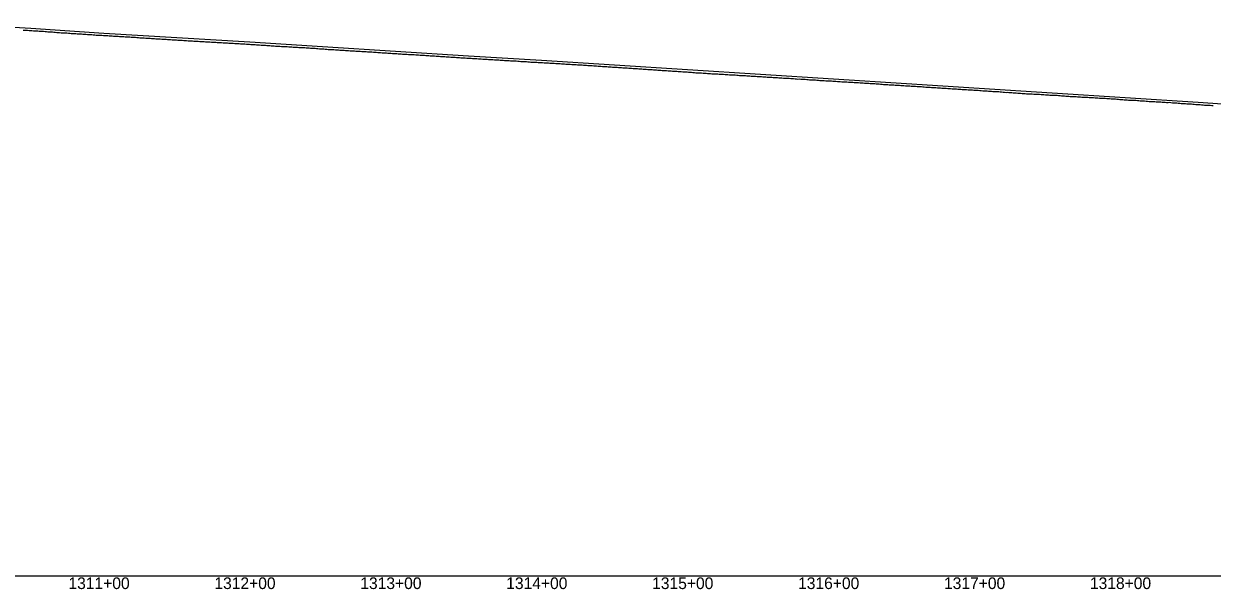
# Model space of a CAD drawing. Extents: x -3793 to 50787, y -1075 to 6138.
# Drawn here: x 18366 to 19180, y 2991 to 3378 of the extents above; entities that cross this region are included whole.
import ezdxf

# ---------------------------------------------------------------- set-up
doc = ezdxf.new("R2010")
doc.units = 0
for name, color, linetype in [('RD_DDB_Profile_EX', 7, 'Continuous'), ('RD_DDB_Profile_PR', 7, 'Continuous'), ('RD_DDB_StaTX', 7, 'Continuous'), ('RD_GPK_Profile_Cell', 7, 'Continuous')]:
    doc.layers.add(name, color=color, linetype=linetype)

msp = doc.modelspace()

# ---------------------------------------------------------------- linework, layer by layer
at = {"layer": 'RD_DDB_Profile_EX'}
for points in [[(18365.154652, 3373.983025), (18366.154155, 3373.89443), (18367.154302, 3373.87296), (18368.15381, 3373.824065), (18369.150116, 3373.745), (18370.154596, 3373.674735), (18371.149772, 3373.654085), (18372.156006, 3373.52486), (18373.151181, 3373.48514), (18374.148925, 3373.4762), (18375.150841, 3373.435495), (18376.151438, 3373.297025), (18377.151622, 3373.256615), (18378.151108, 3373.19736), (18379.146262, 3373.14734), (18380.152509, 3373.06782), (18381.145933, 3372.99768), (18382.145405, 3372.88859), (18383.148431, 3372.84806), (18384.146179, 3372.739235), (18385.148106, 3372.688295), (18386.147571, 3372.62933), (18387.145332, 3372.53072), (18388.147256, 3372.42972), (18389.146719, 3372.370925), (18390.14973, 3372.28016), (18391.147492, 3372.18156), (18392.142601, 3372.14145), (18393.148875, 3372.08171), (18394.142297, 3372.03194), (18395.141744, 3371.99292), (18396.143679, 3371.94197), (18397.142512, 3371.813125), (18398.144447, 3371.731965), (18399.143886, 3371.68279), (18400.13897, 3371.623015), (18401.143598, 3371.56359)], [(18401.143598, 3371.56359), (18402.138678, 3371.51358), (18403.146021, 3371.39453), (18404.139441, 3371.38504), (18405.145737, 3371.33522), (18406.140809, 3371.254595), (18407.142146, 3371.18333), (18408.137223, 3371.133325), (18409.141862, 3371.003015), (18410.137979, 3370.993495), (18411.138271, 3370.883265), (18412.145615, 3370.843295), (18413.139034, 3370.743445), (18414.139318, 3370.68321), (18415.139797, 3370.593895), (18416.140087, 3370.593395), (18417.136204, 3370.533895), (18418.136494, 3370.44307), (18419.14279, 3370.393185), (18420.13726, 3370.32416), (18421.139199, 3370.263645), (18422.138025, 3370.20541), (18423.139964, 3370.164215), (18424.140243, 3370.123325), (18425.14073, 3370.0341), (18426.141015, 3369.933555), (18427.137136, 3369.86281), (18428.141788, 3369.80337), (18429.136854, 3369.753365), (18430.13819, 3369.71277), (18431.140125, 3369.64273), (18432.138958, 3369.564875), (18433.140893, 3369.483465), (18434.134314, 3369.47393), (18435.141661, 3369.393625), (18436.135082, 3369.343775), (18437.138067, 3369.293305), (18438.142716, 3369.243575), (18439.137785, 3369.18389), (18440.139118, 3369.08355), (18441.134192, 3369.043245), (18442.139888, 3369.034035), (18443.14182, 3368.933325), (18444.135242, 3368.873775), (18445.140945, 3368.78398), (18446.136012, 3368.7243), (18447.137344, 3368.68363), (18448.136783, 3368.594085), (18449.137068, 3368.533915), (18450.133182, 3368.484105), (18451.137845, 3368.3844), (18452.133949, 3368.374975), (18453.135886, 3368.28388), (18454.140544, 3368.184175), (18455.136653, 3368.134365), (18456.136941, 3368.074145), (18457.136379, 3368.034655), (18458.137714, 3367.98431), (18459.132777, 3367.92466), (18460.138487, 3367.825195), (18461.133543, 3367.70399), (18462.133838, 3367.714955), (18463.141188, 3367.655715), (18464.134611, 3367.56552), (18465.136539, 3367.524355), (18466.135384, 3367.47565), (18467.137312, 3367.415255), (18468.131775, 3367.315675), (18469.138085, 3367.23499), (18470.131507, 3367.22558), (18471.134478, 3367.13464), (18472.139154, 3367.115755), (18473.134208, 3367.075335), (18474.135543, 3366.965345), (18475.134981, 3366.906765), (18476.136318, 3366.81591), (18477.13137, 3366.765905), (18478.136057, 3366.7258), (18479.132139, 3366.626005), (18480.132442, 3366.60625), (18481.139793, 3366.606655), (18482.133217, 3366.48777), (18483.135141, 3366.427165), (18484.136473, 3366.376655), (18485.138394, 3366.28529), (18486.131818, 3366.235515), (18487.134795, 3366.204235), (18488.135061, 3366.12309), (18489.130145, 3366.07308), (18490.137495, 3365.983165), (18491.139422, 3365.972665), (18492.139676, 3365.92209), (18493.134772, 3365.872075), (18494.136699, 3365.781215), (18495.138626, 3365.73051), (18496.138852, 3365.67998), (18497.133976, 3365.58997), (18498.140242, 3365.55007), (18499.141549, 3365.4998), (18500.136676, 3365.499785), (18501.138603, 3365.3992)], [(18501.138603, 3365.3992), (18502.14053, 3365.288475), (18503.140725, 3365.27781), (18504.13588, 3365.237975), (18505.137807, 3365.17709), (18506.144047, 3365.1272), (18507.144221, 3365.076675), (18508.139392, 3364.986935), (18509.142434, 3364.936485), (18510.144361, 3364.89622), (18511.137784, 3364.806715), (18512.139711, 3364.75619), (18513.141638, 3364.716145), (18514.147852, 3364.60574), (18515.141277, 3364.55586), (18516.143197, 3364.494815), (18517.145118, 3364.454805), (18518.148192, 3364.35444), (18519.141615, 3364.25456), (18520.147816, 3364.233445), (18521.143041, 3364.18342), (18522.149243, 3364.1047), (18523.142666, 3363.99424), (18524.142164, 3364.02388), (18525.144091, 3363.98374), (18526.143584, 3363.84497), (18527.144864, 3363.794715), (18528.144355, 3363.734915), (18529.137776, 3363.63506), (18530.145125, 3363.62494), (18531.138547, 3363.5751), (18532.145896, 3363.485805), (18533.139318, 3363.38595), (18534.138157, 3363.307585), (18535.140088, 3363.296725), (18536.138927, 3363.247725), (18537.140859, 3363.157415), (18538.139698, 3363.058315), (18539.134854, 3362.998115), (18540.139367, 3362.988195), (18541.135617, 3362.88837), (18542.140142, 3362.83864), (18543.134661, 3362.818795), (18544.13412, 3362.7297), (18545.135431, 3362.67937), (18546.134888, 3362.63019), (18547.136202, 3362.54988), (18548.135656, 3362.54062), (18549.136972, 3362.440315), (18550.136424, 3362.351455), (18551.130913, 3362.35191), (18552.137192, 3362.32179), (18553.130613, 3362.24166), (18554.13629, 3362.151925), (18555.131381, 3362.101915), (18556.130214, 3362.04321), (18557.132149, 3362.032785), (18558.130982, 3361.97432), (18559.132917, 3361.91382), (18560.13175, 3361.81522), (18561.12681, 3361.72484), (18562.132518, 3361.684965), (18563.125939, 3361.644695), (18564.133286, 3361.53545), (18565.126707, 3361.495145), (18566.128642, 3361.4349), (18567.127475, 3361.34559), (18568.122512, 3361.245585), (18569.128243, 3361.227135), (18570.123273, 3361.13658), (18571.12799, 3361.02745), (18572.124034, 3360.93707), (18573.128763, 3360.87798), (18574.123782, 3360.759205), (18575.129535, 3360.687855), (18576.124548, 3360.706545), (18577.11956, 3360.647195), (18578.125313, 3360.619735), (18579.120319, 3360.53834), (18580.126079, 3360.43883), (18581.121077, 3360.348095), (18582.125845, 3360.32989), (18583.121836, 3360.280095), (18584.126615, 3360.18962), (18585.121602, 3360.13042), (18586.116012, 3360.08997), (18587.122365, 3359.999265), (18588.115785, 3359.917705), (18589.123128, 3359.877065), (18590.116548, 3359.81807), (18591.123891, 3359.727395), (18592.117311, 3359.66844), (18593.123676, 3359.609495), (18594.119614, 3359.51869), (18595.117453, 3359.501555), (18596.119399, 3359.441885), (18597.113787, 3359.392235), (18598.120159, 3359.269285), (18599.120568, 3359.20985), (18600.116495, 3359.20101), (18601.116904, 3359.10954)], [(18601.116904, 3359.10954), (18602.115724, 3359.01055), (18603.117667, 3358.968955), (18604.119045, 3359.000605), (18605.113439, 3358.900925), (18606.119252, 3358.80137), (18607.121187, 3358.75072), (18608.115582, 3358.660035), (18609.116961, 3358.609725), (18610.114822, 3358.56951), (18611.117727, 3358.49216), (18612.119104, 3358.45081), (18613.112525, 3358.432945), (18614.118346, 3358.333465), (18615.121248, 3358.232905), (18616.11467, 3358.19207), (18617.116043, 3358.13268), (18618.121866, 3358.042185), (18619.11779, 3357.99237), (18620.118188, 3357.91478), (18621.112588, 3357.847235), (18622.118415, 3357.80685), (18623.120335, 3357.77393), (18624.114735, 3357.683305), (18625.116106, 3357.573905), (18626.120957, 3357.574245), (18627.116883, 3357.52446), (18628.118253, 3357.43304), (18629.118636, 3357.341495), (18630.117513, 3357.28372), (18631.120402, 3357.233165), (18632.113827, 3357.210255), (18633.115193, 3357.15996), (18634.116556, 3357.05063), (18635.116952, 3356.9926), (18636.117342, 3356.960055), (18637.111747, 3356.878265), (18638.117587, 3356.86965), (18639.111986, 3356.737695), (18640.11238, 3356.719495), (18641.119742, 3356.61081), (18642.114142, 3356.552195), (18643.12, 3356.493765), (18644.114394, 3356.444095), (18645.114794, 3356.343565), (18646.113695, 3356.31838), (18647.115063, 3356.22674), (18648.110944, 3356.144525), (18649.116819, 3356.09498), (18650.110249, 3356.027655), (18651.11162, 3355.96847), (18652.110522, 3355.87856), (18653.111895, 3355.86944), (18654.106276, 3355.795875), (18655.113641, 3355.75483), (18656.107071, 3355.66361), (18657.112978, 3355.613985), (18658.114352, 3355.522315), (18659.108729, 3355.46395), (18660.114647, 3355.31432), (18661.10808, 3355.347335), (18662.110905, 3355.30543), (18663.109819, 3355.21496), (18664.111199, 3355.11466), (18665.105565, 3355.047905), (18666.110568, 3355.00667), (18667.104933, 3354.956955), (18668.106312, 3354.898135), (18669.106662, 3354.832295), (18670.108047, 3354.79031), (18671.106967, 3354.74151), (18672.107433, 3354.674165), (18673.106858, 3354.500145), (18674.101697, 3354.44184), (18675.107665, 3354.40888), (18676.102498, 3354.417175), (18677.100513, 3354.359765), (18678.107885, 3354.26822), (18679.1027, 3354.17641), (18680.100722, 3354.160935), (18681.100118, 3354.09564), (18682.101525, 3354.05329), (18683.100919, 3354.0201), (18684.100303, 3353.9208), (18685.100846, 3353.87035), (18686.101102, 3353.863295), (18687.094533, 3353.763435), (18688.093907, 3353.706405), (18689.100421, 3353.648775), (18690.094703, 3353.5991), (18691.094066, 3353.54233), (18692.099294, 3353.457995), (18693.09486, 3353.40817), (18694.094212, 3353.359025), (18695.092284, 3353.25251), (18696.094179, 3353.209335), (18697.094345, 3353.16782), (18698.087773, 3353.06796), (18699.094322, 3353.018105), (18700.092413, 3352.969015), (18701.087892, 3352.919175)], [(18701.087892, 3352.919175), (18702.087213, 3352.827255), (18703.092551, 3352.80574), (18704.087208, 3352.755775), (18705.086093, 3352.62132), (18706.092675, 3352.535755), (18707.087313, 3352.528645), (18708.086192, 3352.50144), (18709.088099, 3352.40774), (18710.088795, 3352.378565), (18711.083434, 3352.27859), (18712.085342, 3352.170825), (18713.086812, 3352.09875), (18714.093385, 3352.048945), (18715.088036, 3352.048985), (18716.088712, 3351.962855), (18717.091409, 3351.947705), (18718.086076, 3351.833135), (18719.086742, 3351.77504), (18720.088646, 3351.781485), (18721.083329, 3351.73893), (18722.089435, 3351.63947), (18723.091339, 3351.58862), (18724.091977, 3351.53793), (18725.086672, 3351.487965), (18726.089396, 3351.394815), (18727.090024, 3351.38661), (18728.084733, 3351.2942), (18729.091269, 3351.24439), (18730.091887, 3351.193745), (18731.094617, 3351.09313), (18732.089339, 3351.03553), (18733.089946, 3350.99252), (18734.091847, 3350.941725), (18735.087427, 3350.868775), (18736.092639, 3350.784575), (18737.09454, 3350.675975), (18738.089282, 3350.683755), (18739.089869, 3350.64866), (18740.092626, 3350.598095), (18741.093196, 3350.48962), (18742.087961, 3350.347525), (18743.094462, 3350.321305), (18744.095888, 3350.305175), (18745.090655, 3350.263095), (18746.092562, 3350.186345), (18747.093112, 3350.12798), (18748.095889, 3350.061505), (18749.089317, 3349.969675), (18750.095803, 3349.92782), (18751.097218, 3349.877535), (18752.092011, 3349.8195), (18753.093914, 3349.76083), (18754.091924, 3349.661725), (18755.094704, 3349.603185), (18756.095232, 3349.54453), (18757.094615, 3349.495445), (18758.097397, 3349.40297), (18759.090825, 3349.34505), (18760.092729, 3349.28619), (18761.090736, 3349.203425), (18762.093518, 3349.10291), (18763.095422, 3349.04409), (18764.093427, 3349.045145), (18765.096211, 3348.952695), (18766.089639, 3348.844755), (18767.096118, 3348.794915), (18768.090917, 3348.744935), (18769.092333, 3348.63641), (18770.09881, 3348.586585), (18771.092239, 3348.520585), (18772.095026, 3348.47803), (18773.088454, 3348.37822), (18774.09493, 3348.33651), (18775.089733, 3348.294635), (18776.091147, 3348.18609), (18777.097622, 3348.10251), (18778.091051, 3348.060775), (18779.09384, 3348.043995), (18780.093214, 3347.944905), (18781.093742, 3347.86993), (18782.088548, 3347.81183), (18783.089962, 3347.73577), (18784.096434, 3347.69409), (18785.091243, 3347.594105), (18786.092655, 3347.58552), (18787.09203, 3347.46082), (18788.092554, 3347.410325), (18789.087364, 3347.38589), (18790.094724, 3347.244375), (18791.088151, 3347.220205), (18792.090058, 3347.169305), (18793.096039, 3347.04429), (18794.090846, 3346.98618), (18795.091366, 3346.927375), (18796.093264, 3346.8683), (18797.088983, 3346.776755), (18798.089494, 3346.709555), (18799.095955, 3346.659765), (18800.090284, 3346.58488), (18801.092187, 3346.53409)], [(18801.092187, 3346.53409), (18802.094091, 3346.433305), (18803.087519, 3346.391805), (18804.090336, 3346.341255), (18805.09537, 3346.29156), (18806.090212, 3346.233235), (18807.093031, 3346.149405), (18808.093511, 3345.98258), (18809.088367, 3345.95731), (18810.08884, 3345.93988), (18811.096203, 3345.840215), (18812.091062, 3345.79867), (18813.091532, 3345.806625), (18814.094364, 3345.61351), (18815.087792, 3345.58075), (18816.094224, 3345.53942), (18817.095611, 3345.44756), (18818.097508, 3345.34689), (18819.090937, 3345.297045), (18820.093777, 3345.28792), (18821.094211, 3345.26135), (18822.093628, 3345.17104), (18823.095008, 3345.053335), (18824.096901, 3345.019755), (18825.091279, 3344.944185), (18826.093179, 3344.801895), (18827.093595, 3344.77742), (18828.093971, 3344.71989), (18829.094394, 3344.669235), (18830.096284, 3344.6184), (18831.090673, 3344.4688), (18832.09257, 3344.41797), (18833.093936, 3344.3587), (18834.093364, 3344.3273), (18835.093769, 3344.24431), (18836.089652, 3344.194485), (18837.09457, 3344.085995), (18838.096457, 3344.085275), (18839.090854, 3344.02682), (18840.097258, 3343.959405), (18841.09165, 3343.91859), (18842.093543, 3343.891315), (18843.091491, 3343.81021), (18844.09434, 3343.70955), (18845.087771, 3343.668515), (18846.094179, 3343.627435), (18847.090047, 3343.545125), (18848.09046, 3343.51825), (18849.097827, 3343.409875), (18850.091257, 3343.310075), (18851.09315, 3343.25919), (18852.092054, 3343.278095), (18853.093947, 3343.209795), (18854.088861, 3343.109805), (18855.093787, 3343.02765), (18856.088697, 3342.96892), (18857.08963, 3342.926685), (18858.096034, 3342.88564), (18859.090953, 3342.82685), (18860.092847, 3342.76722), (18861.092275, 3342.677015), (18862.094172, 3342.602755), (18863.089098, 3342.60276), (18864.091005, 3342.49325), (18865.088924, 3342.444205), (18866.090825, 3342.46128), (18867.091748, 3342.392685), (18868.091181, 3342.266875), (18869.093078, 3342.17496), (18870.088021, 3342.20176), (18871.094408, 3342.11972), (18872.089348, 3342.042965), (18873.091258, 3341.933315), (18874.090673, 3341.8842), (18875.091068, 3341.778385), (18876.092972, 3341.72793), (18877.09142, 3341.637315), (18878.093322, 3341.636915), (18879.088277, 3341.586915), (18880.094655, 3341.527995), (18881.089609, 3341.486995), (18882.091523, 3341.41848), (18883.090939, 3341.36011), (18884.092857, 3341.309535), (18885.087818, 3341.17763), (18886.092655, 3341.100755), (18887.093577, 3341.049955), (18888.088546, 3340.98177), (18889.094914, 3340.97283), (18890.090439, 3340.93155), (18891.092362, 3340.780795), (18892.090785, 3340.74061), (18893.092705, 3340.73991), (18894.088256, 3340.689565), (18895.094609, 3340.59889), (18896.088599, 3340.467135), (18897.09053, 3340.47954), (18898.09051, 3340.389295), (18899.092448, 3340.34787), (18900.093374, 3340.32832), (18901.09178, 3340.28833)], [(18901.09178, 3340.28833), (18902.095304, 3340.23745), (18903.089309, 3340.08725), (18904.095639, 3340.006155), (18905.089644, 3339.97479), (18906.093198, 3339.924195), (18907.091582, 3339.884055), (18908.09353, 3339.83363), (18909.087544, 3339.71451), (18910.093861, 3339.605125), (18911.089498, 3339.52625), (18912.091457, 3339.544615), (18913.096731, 3339.454135), (18914.091785, 3339.39454), (18915.094352, 3339.303195), (18916.093752, 3339.22313), (18917.094676, 3339.20312), (18918.088706, 3339.162645), (18919.096657, 3339.11261), (18920.09069, 3339.02217), (18921.092659, 3338.922715), (18922.091013, 3338.883165), (18923.094658, 3338.83223), (18924.088702, 3338.791835), (18925.094978, 3338.781245), (18926.095891, 3338.63067), (18927.125708, 3338.59126), (18927.678407, 3338.55076), (18928.684784, 3338.49095), (18929.679882, 3338.49094), (18930.679663, 3338.360525), (18931.676021, 3338.330655), (18932.680852, 3338.310725), (18933.682171, 3338.27014), (18934.677281, 3338.140095), (18935.678314, 3338.08992), (18936.679642, 3338.00931), (18937.679792, 3337.96997), (18938.679559, 3337.89974), (18939.682153, 3337.849515), (18940.675711, 3337.789505), (18941.677038, 3337.659415), (18942.683387, 3337.52905), (18943.678222, 3337.56918), (18944.679549, 3337.518675), (18945.674687, 3337.42883), (18946.679456, 3337.389155), (18947.68206, 3337.34907), (18948.675618, 3337.279655), (18949.676946, 3337.219295), (18950.678274, 3337.219105), (18951.678129, 3337.11847), (18952.679457, 3336.96796), (18953.680785, 3336.917455), (18954.674343, 3336.807265), (18955.676974, 3336.756865), (18956.675526, 3336.747395), (18957.676854, 3336.686435), (18958.678181, 3336.556515), (18959.673043, 3336.51717), (18960.679365, 3336.46725), (18961.67453, 3336.39654), (18962.679248, 3336.30712), (18963.675707, 3336.277885), (18964.675433, 3336.25685), (18965.675592, 3336.14722), (18966.676921, 3336.07761), (18967.671777, 3336.03815), (18968.678103, 3336.017615), (18969.679433, 3335.87747), (18970.677992, 3335.86781), (18971.680615, 3335.807135), (18972.674172, 3335.71757), (18973.680501, 3335.64706), (18974.675659, 3335.597045), (18975.681689, 3335.507745), (18976.676839, 3335.45773), (18977.677866, 3335.417755), (18978.676435, 3335.338845), (18979.677459, 3335.22845), (18980.67389, 3335.21837), (18981.67993, 3335.12809), (18982.674764, 3335.09874), (18983.680817, 3334.96935), (18984.674375, 3334.94933), (18985.675405, 3334.878845), (18986.675267, 3334.8001), (18987.676298, 3334.699805), (18988.672671, 3334.649965), (18989.678741, 3334.620545), (18990.672298, 3334.53067), (18991.678383, 3334.471295), (18992.673188, 3334.38158), (18993.674225, 3334.34113), (18994.674083, 3334.24228), (18995.67512, 3334.182135), (18996.670205, 3334.141945), (18997.676306, 3334.1022), (18998.677343, 3334.012675), (18999.677207, 3333.893245), (19000.678246, 3333.852655)], [(19000.678246, 3333.852655), (19001.67303, 3333.793265), (19002.677932, 3333.75322), (19003.672713, 3333.71318), (19004.675255, 3333.65309), (19005.675112, 3333.594535), (19006.676156, 3333.54421), (19007.670923, 3333.454135), (19008.675856, 3333.385265), (19009.670621, 3333.335635), (19010.676775, 3333.255115), (19011.671531, 3333.214875), (19012.674051, 3333.114485), (19013.673904, 3333.0966), (19014.673765, 3333.04609), (19015.67481, 3332.95524), (19016.674682, 3332.865625), (19017.675728, 3332.81536), (19018.670472, 3332.806255), (19019.67665, 3332.706665), (19020.671658, 3332.656665), (19021.672708, 3332.606365), (19022.672573, 3332.466635), (19023.673625, 3332.44778), (19024.668353, 3332.38884), (19025.674545, 3332.330105), (19026.669536, 3332.230105), (19027.669424, 3332.11658), (19028.675885, 3332.057425), (19029.670881, 3331.948165), (19030.677343, 3331.82055), (19031.672338, 3331.82055), (19032.67366, 3331.80694), (19033.672362, 3331.807785), (19034.673677, 3331.716465), (19035.668677, 3331.616465), (19036.675136, 3331.52584), (19037.670134, 3331.475835), (19038.67146, 3331.253345), (19039.670154, 3331.33528), (19040.671472, 3331.30694), (19041.671611, 3331.25766), (19042.67293, 3331.175645), (19043.673067, 3331.03544), (19044.674389, 3330.96645), (19045.674523, 3330.87631), (19046.668082, 3330.82642), (19047.669405, 3330.78519), (19048.669536, 3330.7357), (19049.670861, 3330.576025), (19050.67099, 3330.53578), (19051.672317, 3330.526115), (19052.671022, 3330.41766), (19053.666001, 3330.37681), (19054.672476, 3330.326905), (19055.667453, 3330.276905), (19056.673929, 3330.227), (19057.668905, 3330.136125), (19058.675381, 3330.08621), (19059.66894, 3330.036305), (19060.675422, 3330.040955), (19061.670392, 3330.000045), (19062.665361, 3329.836395), (19063.671842, 3329.777405), (19064.66681, 3329.777405), (19065.671886, 3329.727615), (19066.66685, 3329.64571), (19067.673337, 3329.595785), (19068.668299, 3329.477715), (19069.674787, 3329.36879), (19070.669747, 3329.35977), (19071.669859, 3329.355265), (19072.669794, 3329.337025), (19073.669915, 3329.287555), (19074.670979, 3329.15523), (19075.672305, 3329.104915), (19076.672222, 3328.95467), (19077.668329, 3328.8819), (19078.668248, 3328.845415), (19079.669572, 3328.80839), (19080.670627, 3328.808075), (19081.665613, 3328.74888), (19082.666671, 3328.544655), (19083.668001, 3328.54428), (19084.67302, 3328.412955), (19085.669183, 3328.413025), (19086.669069, 3328.41283), (19087.670389, 3328.321935), (19088.671437, 3328.22184), (19089.666453, 3328.20307), (19090.667504, 3328.11233), (19091.66883, 3328.07156), (19092.668676, 3328.04284), (19093.671202, 3327.99257), (19094.66476, 3327.91177), (19095.666085, 3327.87114), (19096.672224, 3327.790425), (19097.673539, 3327.7), (19098.668313, 3327.730785), (19099.669636, 3327.661325), (19100.66945, 3327.62085)], [(19100.66945, 3327.62085), (19101.671997, 3327.5), (19102.667071, 3327.420715), (19103.666877, 3327.341155), (19104.669441, 3327.30074), (19105.669231, 3327.30051), (19106.665572, 3327.30059), (19107.665363, 3327.14007), (19108.66669, 3327.08002), (19109.666547, 3327.030795), (19110.672929, 3326.98087), (19111.666488, 3326.880965), (19112.674118, 3326.890995), (19113.667678, 3326.84108), (19114.66783, 3326.76226), (19115.668867, 3326.571775), (19116.669018, 3326.522345), (19117.670056, 3326.531845), (19118.670206, 3326.451675), (19119.665266, 3326.301675), (19120.670178, 3326.24216), (19121.665234, 3326.192155), (19122.665377, 3326.05216), (19123.666702, 3326.01333), (19124.666563, 3325.892845), (19125.67299, 3325.933395), (19126.668027, 3325.89291), (19127.666697, 3325.85286), (19128.668015, 3325.74561), (19129.668159, 3325.64642), (19130.669479, 3325.583645), (19131.669347, 3325.584385), (19132.664362, 3325.53438), (19133.670808, 3325.484465), (19134.664367, 3325.39391), (19135.664502, 3325.25363), (19136.665826, 3325.162655), (19137.664522, 3325.072255), (19138.665838, 3325.112755), (19139.667143, 3325.153905), (19140.662134, 3324.94078), (19141.66717, 3324.87646), (19142.667306, 3324.87706), (19143.668625, 3324.83983), (19144.667347, 3324.75), (19145.662318, 3324.700005), (19146.664792, 3324.640355), (19147.671268, 3324.549625), (19148.664827, 3324.44978), (19149.666148, 3324.43991), (19150.661132, 3324.480735), (19151.666182, 3324.38108), (19152.667495, 3324.23025), (19153.663644, 3324.11208), (19154.663538, 3324.111345), (19155.670002, 3324.111525), (19156.664994, 3323.99845), (19157.666318, 3323.88845), (19158.659877, 3323.779345), (19159.666335, 3323.77023), (19160.668827, 3323.728895), (19161.662386, 3323.62908), (19162.66371, 3323.487615), (19163.658723, 3323.478245), (19164.663719, 3323.36925), (19165.666219, 3323.359215), (19166.660958, 3323.319045), (19167.662011, 3323.149835), (19168.667002, 3323.068975), (19169.663193, 3323.05053), (19170.664245, 3323.050025), (19171.657803, 3322.91897), (19172.663981, 3322.860265), (19173.665029, 3322.68783), (19174.661215, 3322.638035), (19175.66109, 3322.59683), (19176.667267, 3322.5693), (19177.662004, 3322.47904), (19178.663326, 3322.428225), (19179.658062, 3322.37863), (19180.659115, 3322.30633)]]:
    msp.add_lwpolyline(points, dxfattribs=at)
at = {"layer": 'RD_DDB_Profile_PR'}
msp.add_lwpolyline([(18320.37, 3378.3055), (18370.37, 3375.2705), (18420.37, 3371.9105), (18470.37, 3368.8045), (18520.37, 3365.8225), (18570.37, 3362.71), (18620.37, 3359.498), (18670.37, 3356.3775), (18720.37, 3353.3695), (18770.37, 3350.169), (18820.37, 3346.8805), (18870.37, 3343.779), (18920.37, 3340.595), (18970.37, 3337.471), (19020.37, 3334.272), (19070.37, 3330.9625), (19120.37, 3327.86), (19170.37, 3324.65), (19220.37, 3321.1005)], dxfattribs=at)
at = {"layer": 'RD_GPK_Profile_Cell'}
msp.add_line((1000, 3000), (46549.603806, 3000), dxfattribs=at)

# ---------------------------------------------------------------- texts
at = {"layer": 'RD_DDB_StaTX'}
for s, p in [('1311+00', (18396.161484, 2991)), ('1311+00', (18396.165471, 2991)), ('1312+00', (18496.161484, 2991)), ('1312+00', (18496.165471, 2991)), ('1313+00', (18596.161484, 2991)), ('1313+00', (18596.165471, 2991)), ('1314+00', (18696.161484, 2991)), ('1314+00', (18696.165471, 2991)), ('1315+00', (18796.161484, 2991)), ('1315+00', (18796.165471, 2991)), ('1316+00', (18896.161484, 2991)), ('1316+00', (18896.165471, 2991)), ('1317+00', (18996.161484, 2991)), ('1317+00', (18996.165471, 2991)), ('1318+00', (19096.161484, 2991)), ('1318+00', (19096.165471, 2991))]:
    msp.add_text(s, height=8, dxfattribs=at).set_placement(p)

doc.saveas('drawing.dxf')
